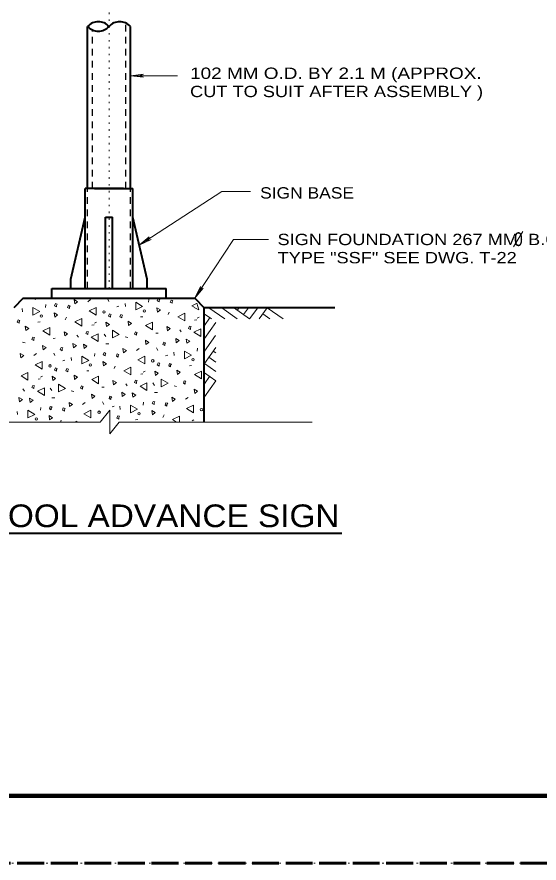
# Model space of a CAD drawing. Extents: x 312583 to 312854, y 144419 to 144597.
# Drawn here: x 312766.7 to 312801.7, y 144418.6 to 144475.3 of the extents above; entities that cross this region are included whole.
import ezdxf
from ezdxf.enums import TextEntityAlignment as Align

# ---------------------------------------------------------------- set-up
doc = ezdxf.new("R2010")
doc.units = 0
doc.header["$LTSCALE"] = 0.3
for name, pattern in [('DOTTED', [1.5, 0.3, -1.2]), ('LONG_DASHED', [7.5, 6, -1.5]), ('SHORT_DASHED', [2.7, 1.5, -1.2])]:
    doc.linetypes.add(name, pattern=pattern)
for name, color, linetype, lineweight in [('1', 7, 'Continuous', 40), ('2', 7, 'Continuous', 13), ('62', 7, 'DOTTED', 13), ('63', 7, 'LONG_DASHED', 60)]:
    doc.layers.add(name, color=color, linetype=linetype, lineweight=lineweight)

msp = doc.modelspace()

# ---------------------------------------------------------------- linework, layer by layer
at = {"layer": '1', "linetype": 'DOTTED', "lineweight": 13}
msp.add_line((312772.852, 144457.0926), (312772.852, 144496.5069), dxfattribs=at)
at = {"layer": '1', "linetype": 'SHORT_DASHED', "lineweight": 25}
for p, q in [((312773.9713, 144463.8009), (312773.9713, 144474.8946)), ((312771.7326, 144463.8009), (312771.7326, 144474.4269)), ((312771.4183, 144457.0926), (312771.4183, 144463.8009)), ((312774.2933, 144457.0926), (312774.2933, 144463.8009))]:
    msp.add_line(p, q, dxfattribs=at)
at = {"layer": '1'}
for p, q in [((312771.4183, 144463.8009), (312771.4183, 144474.6646)), ((312774.2933, 144463.8009), (312774.2933, 144474.6646)), ((312771.2573, 144457.0926), (312771.2573, 144463.8009)), ((312773.8256, 144463.8009), (312771.2573, 144463.8009)), ((312771.8783, 144463.8009), (312774.4466, 144463.8009)), ((312774.4466, 144457.0926), (312774.4466, 144463.8009)), ((312770.299, 144457.7289), (312771.2573, 144461.8843)), ((312772.6143, 144461.8843), (312773.0896, 144461.8843)), ((312772.6143, 144457.0926), (312772.6143, 144461.8843)), ((312773.0896, 144457.0926), (312773.0896, 144461.8843)), ((312775.405, 144457.7289), (312774.4466, 144461.8843)), ((312770.299, 144457.0926), (312770.299, 144457.7289)), ((312770.299, 144457.0926), (312770.299, 144457.7289)), ((312775.405, 144457.0926), (312775.405, 144457.7289)), ((312769.0186, 144456.4563), (312769.0186, 144457.0926)), ((312769.0186, 144457.0926), (312776.6853, 144457.0926)), ((312776.6853, 144456.4563), (312776.6853, 144457.0926)), ((312767.102, 144456.4563), (312766.4656, 144455.8123)), ((312767.102, 144456.4563), (312778.602, 144456.4563)), ((312778.602, 144456.4563), (312779.2383, 144455.8123)), ((312787.9936, 144455.8123), (312779.2383, 144455.8123)), ((312779.2383, 144448.1456), (312779.2383, 144455.8123))]:
    msp.add_line(p, q, dxfattribs=at)
at = {"layer": '1', "lineweight": 158}
msp.add_line((312616.5, 144423.0846), (312849, 144423.0846), dxfattribs=at)
at = {"layer": '1'}
for centre, start, end in [((312772.1339, 144474.0125), 42.07502, 137.92498), ((312773.5714, 144474.0125), 42.07502, 137.92498), ((312772.1339, 144475.3103), 222.07502, 317.92498)]:
    msp.add_arc(centre, 0.9683, start, end, dxfattribs=at)
at = {"layer": '2'}
for p, q in [((312774.2933, 144471.3603), (312775.1596, 144471.4676)), ((312774.2933, 144471.3603), (312777.452, 144471.3603)), ((312774.2933, 144471.3603), (312775.1596, 144471.2529)), ((312775.1596, 144471.4676), (312774.8836, 144471.3603)), ((312775.1596, 144471.2529), (312774.8836, 144471.3603)), ((312780.419, 144463.6016), (312774.8836, 144459.9906)), ((312780.419, 144463.6016), (312782.351, 144463.6016)), ((312799.9739, 144459.8899), (312800.6102, 144460.9172)), ((312774.8836, 144459.9906), (312775.5506, 144460.5579)), ((312774.8836, 144459.9906), (312775.6733, 144460.3739)), ((312775.5506, 144460.5579), (312775.382, 144460.3126)), ((312775.6733, 144460.3739), (312775.382, 144460.3126)), ((312781.1933, 144460.3816), (312778.602, 144456.4563)), ((312781.1933, 144460.3816), (312783.5393, 144460.3816)), ((312778.602, 144456.4563), (312778.993, 144457.2383)), ((312778.993, 144457.2383), (312778.9316, 144456.9469)), ((312778.602, 144456.4563), (312779.1693, 144457.1156)), ((312779.1693, 144457.1156), (312778.9316, 144456.9469)), ((312767.194, 144456.4563), (312767.2016, 144456.3949)), ((312767.2016, 144456.3949), (312767.2783, 144456.4563)), ((312767.8916, 144456.4563), (312767.907, 144456.3566)), ((312767.907, 144456.3566), (312768.0373, 144456.4563)), ((312771.6023, 144456.3489), (312771.426, 144456.2109)), ((312772.76, 144456.3873), (312772.8443, 144456.2186)), ((312773.9253, 144456.0959), (312773.9483, 144455.8889)), ((312775.4893, 144456.1726), (312775.5123, 144456.3566)), ((312777.4366, 144456.4563), (312777.4443, 144456.4103)), ((312777.4443, 144456.4103), (312777.498, 144456.4563)), ((312778.4103, 144455.9273), (312778.7246, 144456.0959)), ((312778.8703, 144455.6589), (312778.7476, 144456.1113)), ((312767.033, 144455.7509), (312767.056, 144455.5439)), ((312768.597, 144455.8276), (312768.62, 144456.0193)), ((312773.3656, 144455.8659), (312773.5113, 144455.9043)), ((312776.8846, 144455.5133), (312776.808, 144455.3446)), ((312778.4026, 144455.9426), (312778.602, 144455.8199)), ((312778.6096, 144455.8123), (312778.8703, 144455.6589)), ((312780.6106, 144455.0533), (312779.5373, 144455.8123)), ((312781.4463, 144455.0533), (312780.4113, 144455.7969)), ((312782.282, 144455.0533), (312781.1933, 144455.8276)), ((312781.569, 144455.8123), (312781.4463, 144455.6436)), ((312782.1976, 144455.8123), (312781.868, 144455.3523)), ((312782.8263, 144455.8123), (312782.282, 144455.0533)), ((312783.455, 144455.8123), (312782.9106, 144455.0533)), ((312784.5206, 144455.0533), (312783.455, 144455.8123)), ((312769.9923, 144455.1683), (312769.9156, 144454.9996)), ((312774.968, 144455.1913), (312775.1213, 144455.1989)), ((312778.5943, 144454.9843), (312778.74, 144455.0073)), ((312778.763, 144455.1146), (312778.8933, 144455.1836)), ((312779.729, 144455.0533), (312779.2383, 144455.3983)), ((312779.246, 144454.6239), (312779.591, 144455.1069)), ((312783.639, 144455.0533), (312783.156, 144455.3983)), ((312768.0833, 144454.8463), (312768.229, 144454.8539)), ((312771.702, 144454.6393), (312771.8476, 144454.6623)), ((312771.8706, 144454.7696), (312772.001, 144454.8386)), ((312777.59, 144454.3249), (312777.6973, 144454.1869)), ((312779.246, 144453.7423), (312780.0126, 144454.8156)), ((312769.0953, 144453.7499), (312769.2486, 144453.7576)), ((312770.6976, 144453.9799), (312770.805, 144453.8419)), ((312772.5146, 144454.0413), (312772.6373, 144453.8803)), ((312773.9406, 144453.8496), (312774.1093, 144453.8036)), ((312775.9876, 144454.0949), (312776.141, 144454.1026)), ((312779.246, 144452.8989), (312779.9896, 144453.9416)), ((312767.056, 144453.5046), (312767.2246, 144453.4586)), ((312772.6296, 144453.3819), (312772.8366, 144453.3973)), ((312767.9913, 144452.7303), (312767.8073, 144452.5999)), ((312769.1413, 144452.7686), (312769.2256, 144452.5999)), ((312771.8706, 144452.5539), (312771.8936, 144452.7456)), ((312774.876, 144453.0753), (312774.6996, 144452.9449)), ((312776.026, 144453.1136), (312776.118, 144452.9449)), ((312776.6393, 144452.5923), (312776.785, 144452.6306)), ((312777.199, 144452.8223), (312777.222, 144452.6153)), ((312778.7553, 144452.8989), (312778.7783, 144453.0906)), ((312779.246, 144452.0709), (312780.0203, 144453.1519)), ((312780.0126, 144452.7839), (312779.8363, 144452.8989)), ((312769.747, 144452.2473), (312769.8926, 144452.2856)), ((312770.3066, 144452.4773), (312770.3296, 144452.2703)), ((312780.0126, 144451.5266), (312779.246, 144452.0709)), ((312780.0126, 144452.1553), (312779.545, 144452.4849)), ((312771.357, 144451.5726), (312771.5026, 144451.5803)), ((312773.266, 144451.8946), (312773.1893, 144451.7259)), ((312775.1443, 144451.4959), (312775.2746, 144451.5649)), ((312778.2416, 144451.9176), (312778.3873, 144451.9253)), ((312768.091, 144451.0206), (312768.2366, 144451.0436)), ((312768.2596, 144451.1509), (312768.3823, 144451.2199)), ((312774.9756, 144451.3656), (312775.1213, 144451.3886)), ((312780.0126, 144450.8979), (312779.246, 144451.4423)), ((312779.246, 144450.7139), (312779.591, 144451.1969)), ((312767.079, 144450.3613), (312767.1863, 144450.2233)), ((312768.896, 144450.4226), (312769.0186, 144450.2616)), ((312772.369, 144450.4763), (312772.5223, 144450.4839)), ((312773.9713, 144450.7063), (312774.0786, 144450.5683)), ((312775.7806, 144450.7676), (312775.9033, 144450.6066)), ((312777.2143, 144450.5759), (312777.383, 144450.5299)), ((312779.246, 144449.8323), (312780.0126, 144450.8979)), ((312770.322, 144450.2309), (312770.4983, 144450.1849)), ((312775.9033, 144450.1159), (312776.1103, 144450.1236)), ((312778.1496, 144449.8016), (312777.9733, 144449.6713)), ((312769.011, 144449.7709), (312769.218, 144449.7786)), ((312771.2573, 144449.4566), (312771.081, 144449.3263)), ((312772.415, 144449.5026), (312772.4993, 144449.3263)), ((312775.1443, 144449.2803), (312775.1673, 144449.4719)), ((312766.688, 144448.8586), (312766.711, 144448.6516)), ((312768.252, 144448.9353), (312768.275, 144449.1269)), ((312773.0513, 144449.1653), (312773.197, 144449.2036)), ((312773.5803, 144449.2036), (312773.6033, 144448.9966)), ((312757.649, 144448.1456), (312772.2616, 144448.1456)), ((312769.6473, 144448.2759), (312769.5936, 144448.1456)), ((312773.542, 144448.1456), (312786.4833, 144448.1456)), ((312774.6306, 144448.2989), (312774.7763, 144448.3066)), ((312776.5396, 144448.6209), (312776.463, 144448.4523)), ((312778.418, 144448.2223), (312778.5483, 144448.2913))]:
    msp.add_line(p, q, dxfattribs=at)
at = {"layer": '2', "lineweight": 40}
msp.add_line((312749.5561, 144440.7036), (312788.4573, 144440.7036), dxfattribs=at)
at = {"layer": '2'}
for points in [[(312769.3253, 144455.9656), (312769.3713, 144456.0423), (312769.2563, 144456.0806), (312769.195, 144455.9273), (312769.3253, 144455.8583)], [(312770.552, 144456.0653), (312770.7436, 144456.2109), (312770.5136, 144456.3566)], [(312774.6383, 144456.1726), (312774.6383, 144455.6589), (312775.106, 144455.8966)], [(312776.2176, 144456.3106), (312776.2636, 144456.3873), (312776.1486, 144456.4256), (312776.0873, 144456.2723), (312776.2176, 144456.2033)], [(312777.084, 144456.2109), (312777.1376, 144456.2876), (312777.015, 144456.3259), (312776.9613, 144456.1726), (312777.084, 144456.1036)], [(312767.746, 144455.8276), (312767.746, 144455.3139), (312768.2136, 144455.5516)], [(312769.2103, 144455.1759), (312769.402, 144455.3293), (312769.172, 144455.4673)], [(312770.1993, 144455.8659), (312770.2453, 144455.9426), (312770.1303, 144455.9809), (312770.069, 144455.8276), (312770.1993, 144455.7586)], [(312771.978, 144455.3139), (312771.978, 144455.8276), (312771.5103, 144455.5976)], [(312776.1026, 144455.5209), (312776.2943, 144455.6743), (312776.0566, 144455.8123)], [(312766.8183, 144454.8846), (312766.8643, 144454.9613), (312766.7493, 144454.9996), (312766.688, 144454.8463), (312766.8183, 144454.7773)], [(312771.035, 144454.5779), (312771.035, 144455.0916), (312770.5673, 144454.8616)], [(312772.944, 144455.2756), (312772.99, 144455.3599), (312772.875, 144455.3983), (312772.8136, 144455.2449), (312772.944, 144455.1759)], [(312773.7106, 144455.2296), (312773.7566, 144455.3063), (312773.6416, 144455.3446), (312773.5803, 144455.1913), (312773.7106, 144455.1223)], [(312774.163, 144454.6163), (312774.3546, 144454.7619), (312774.1246, 144454.9076)], [(312777.9273, 144454.9229), (312777.9273, 144455.4366), (312777.4596, 144455.1989)], [(312767.2783, 144454.2713), (312767.47, 144454.4169), (312767.2323, 144454.5626)], [(312768.8806, 144453.9799), (312768.8806, 144454.4936), (312768.413, 144454.2636)], [(312772.6833, 144454.5396), (312772.8826, 144454.6853), (312772.645, 144454.8309)], [(312775.773, 144454.3249), (312775.773, 144454.8386), (312775.3053, 144454.6086)], [(312776.762, 144454.2636), (312776.9613, 144454.4093), (312776.7236, 144454.5473)], [(312778.3106, 144454.4553), (312778.3643, 144454.5396), (312778.2416, 144454.5703), (312778.188, 144454.4169), (312778.3106, 144454.3479)], [(312779.016, 144453.8879), (312779.016, 144454.4016), (312778.5483, 144454.1716)], [(312767.7996, 144453.7269), (312767.8456, 144453.8036), (312767.7306, 144453.8419), (312767.6693, 144453.6886), (312767.7996, 144453.6196)], [(312769.8773, 144453.9186), (312770.069, 144454.0643), (312769.839, 144454.2023)], [(312771.426, 144454.1103), (312771.472, 144454.1946), (312771.357, 144454.2253), (312771.2956, 144454.0719), (312771.426, 144454.0029)], [(312772.1236, 144453.5429), (312772.1236, 144454.0566), (312771.656, 144453.8266)], [(312773.0743, 144454.3019), (312773.0743, 144453.7806), (312773.542, 144454.0183)], [(312774.692, 144454.0719), (312774.738, 144454.1486), (312774.623, 144454.1869), (312774.5616, 144454.0336), (312774.692, 144453.9646)], [(312768.436, 144452.9909), (312768.6353, 144453.1366), (312768.3976, 144453.2823)], [(312770.4753, 144453.1213), (312770.667, 144453.2669), (312770.4293, 144453.4049)], [(312771.1806, 144453.0829), (312771.3723, 144453.2286), (312771.1346, 144453.3666)], [(312775.3283, 144453.3359), (312775.52, 144453.4816), (312775.29, 144453.6273)], [(312776.5933, 144453.3819), (312776.647, 144453.4586), (312776.5243, 144453.4969), (312776.4706, 144453.3436), (312776.5933, 144453.2746)], [(312777.36, 144453.4663), (312777.5516, 144453.6119), (312777.3216, 144453.7499)], [(312778.0653, 144453.4279), (312778.2646, 144453.5736), (312778.027, 144453.7116)], [(312766.9333, 144452.4466), (312767.1326, 144452.5999), (312766.895, 144452.7379)], [(312769.7086, 144453.0369), (312769.7546, 144453.1136), (312769.6396, 144453.1519), (312769.5783, 144452.9986), (312769.7086, 144452.9296)], [(312772.599, 144452.6919), (312772.645, 144452.7686), (312772.53, 144452.8069), (312772.4686, 144452.6536), (312772.599, 144452.5846)], [(312773.473, 144452.5923), (312773.519, 144452.6689), (312773.3963, 144452.7073), (312773.3426, 144452.5539), (312773.473, 144452.4849)], [(312773.8256, 144452.7916), (312774.0173, 144452.9449), (312773.7873, 144453.0829)], [(312777.912, 144452.8989), (312777.912, 144452.3853), (312778.3796, 144452.6229)], [(312768.3593, 144451.6953), (312768.3593, 144452.2089), (312767.8916, 144451.9789)], [(312771.0196, 144452.5539), (312771.0196, 144452.0403), (312771.4873, 144452.2779)], [(312772.484, 144451.9099), (312772.6756, 144452.0556), (312772.438, 144452.1936)], [(312775.2516, 144452.0403), (312775.2516, 144452.5539), (312774.784, 144452.3239)], [(312776.2176, 144452.0096), (312776.2636, 144452.0863), (312776.1486, 144452.1246), (312776.0873, 144451.9713), (312776.2176, 144451.9023)], [(312776.9843, 144451.9559), (312777.0303, 144452.0326), (312776.9076, 144452.0709), (312776.854, 144451.9176), (312776.9843, 144451.8486)], [(312769.3253, 144451.6646), (312769.3713, 144451.7413), (312769.2563, 144451.7796), (312769.195, 144451.6263), (312769.3253, 144451.5573)], [(312770.092, 144451.6109), (312770.138, 144451.6876), (312770.023, 144451.7259), (312769.9616, 144451.5726), (312770.092, 144451.5036)], [(312774.3086, 144451.3043), (312774.3086, 144451.8179), (312773.841, 144451.5879)], [(312775.957, 144451.2659), (312776.1486, 144451.4193), (312775.9186, 144451.5573)], [(312777.4366, 144451.3426), (312777.6283, 144451.4883), (312777.3983, 144451.6339)], [(312779.0466, 144451.0513), (312779.0466, 144451.5649), (312778.579, 144451.3349)], [(312767.4163, 144450.9593), (312767.4163, 144451.4729), (312766.9486, 144451.2429)], [(312769.0723, 144450.9209), (312769.264, 144451.0743), (312769.0263, 144451.2123)], [(312770.5443, 144450.9976), (312770.7436, 144451.1509), (312770.506, 144451.2889)], [(312772.1543, 144450.7063), (312772.1543, 144451.2199), (312771.6866, 144450.9899)], [(312773.151, 144450.6449), (312773.3426, 144450.7906), (312773.105, 144450.9286)], [(312774.6996, 144450.8366), (312774.7456, 144450.9209), (312774.6306, 144450.9516), (312774.5693, 144450.8059), (312774.6996, 144450.7293)], [(312776.348, 144451.0283), (312776.348, 144450.5146), (312776.8156, 144450.7446)], [(312767.8073, 144450.4916), (312767.8533, 144450.5759), (312767.7383, 144450.6066), (312767.677, 144450.4609), (312767.8073, 144450.3843)], [(312768.5126, 144449.9243), (312768.5126, 144450.4379), (312768.045, 144450.2079)], [(312769.4633, 144450.6833), (312769.4633, 144450.1696), (312769.9233, 144450.3996)], [(312771.0733, 144450.4533), (312771.1193, 144450.5299), (312771.0043, 144450.5683), (312770.943, 144450.4149), (312771.0733, 144450.3459)], [(312775.3973, 144450.2693), (312775.3973, 144450.7829), (312774.9296, 144450.5529)], [(312777.9656, 144450.7983), (312778.0116, 144450.8749), (312777.8966, 144450.9133), (312777.8353, 144450.7599), (312777.9656, 144450.6909)], [(312778.602, 144450.0623), (312778.7936, 144450.2156), (312778.5636, 144450.3536)], [(312766.8566, 144449.5026), (312767.0483, 144449.6483), (312766.8106, 144449.7939)], [(312771.7096, 144449.7173), (312771.9013, 144449.8706), (312771.6713, 144450.0086)], [(312772.9823, 144449.7633), (312773.0283, 144449.8399), (312772.9056, 144449.8783), (312772.852, 144449.7249), (312772.9823, 144449.6559)], [(312773.7413, 144449.8476), (312773.9406, 144449.9933), (312773.703, 144450.1389)], [(312774.4543, 144449.8093), (312774.646, 144449.9549), (312774.4083, 144450.0929)], [(312777.0993, 144449.5256), (312777.291, 144449.6713), (312777.061, 144449.8093)], [(312767.562, 144449.4643), (312767.7536, 144449.6099), (312767.5236, 144449.7479)], [(312770.207, 144449.1806), (312770.3986, 144449.3263), (312770.1686, 144449.4643)], [(312774.2933, 144449.2879), (312774.2933, 144448.7666), (312774.761, 144449.0043)], [(312775.8726, 144449.4183), (312775.9186, 144449.5026), (312775.8036, 144449.5333), (312775.7423, 144449.3799), (312775.8726, 144449.3109)], [(312776.739, 144449.3186), (312776.7926, 144449.4029), (312776.67, 144449.4336), (312776.6163, 144449.2803), (312776.739, 144449.2113)], [(312778.5253, 144448.7666), (312778.5253, 144449.2803), (312778.0576, 144449.0503)], [(312767.401, 144448.9429), (312767.401, 144448.4216), (312767.8686, 144448.6593)], [(312768.9803, 144449.0733), (312769.0263, 144449.1576), (312768.9113, 144449.1883), (312768.85, 144449.0349), (312768.9803, 144448.9659)], [(312769.8543, 144448.9736), (312769.9003, 144449.0579), (312769.7853, 144449.0886), (312769.724, 144448.9353), (312769.8543, 144448.8663)], [(312771.633, 144448.4216), (312771.633, 144448.9353), (312771.1653, 144448.7053)], [(312775.7576, 144448.6363), (312775.9493, 144448.7819), (312775.7116, 144448.9199)], [(312768.8653, 144448.2913), (312769.057, 144448.4369), (312768.827, 144448.5749)], [(312773.5036, 144448.4446), (312773.5496, 144448.5289), (312773.4346, 144448.5596), (312773.3733, 144448.4063), (312773.5036, 144448.3373)]]:
    msp.add_lwpolyline(points, close=True, dxfattribs=at)
for points in [[(312773.542, 144448.1456), (312772.9056, 144447.3483), (312772.9056, 144448.9429), (312772.2616, 144448.1456)], [(312770.69, 144448.1456), (312770.69, 144448.1993), (312770.5826, 144448.1456)], [(312777.5746, 144448.1456), (312777.5823, 144448.5443), (312777.1146, 144448.3143), (312777.383, 144448.1456)], [(312779.2383, 144448.2529), (312779.1923, 144448.2836), (312779.2076, 144448.1456)]]:
    msp.add_lwpolyline(points, dxfattribs=at)
for centre, radius in [((312772.5111, 144455.5232), 0.0865), ((312775.2108, 144455.5936), 0.0784), ((312768.321, 144455.2489), 0.0784), ((312771.5935, 144451.9764), 0.0784), ((312775.7836, 144452.2506), 0.0865), ((312778.4834, 144452.3211), 0.0784), ((312768.8938, 144451.9059), 0.0865), ((312772.1824, 144448.8026), 0.0865), ((312774.8661, 144448.7038), 0.0784), ((312779.0562, 144448.978), 0.0865), ((312767.9763, 144448.3591), 0.0784)]:
    msp.add_circle(centre, radius, dxfattribs=at)
at = {"layer": '62'}
msp.add_lwpolyline([(312601.2, 144418.5846), (312853.5, 144418.5846), (312853.5, 144596.7846)], dxfattribs=at)
at = {"layer": '63'}
msp.add_line((312851.75, 144418.5846), (312583.526, 144418.5846), dxfattribs=at)

# ---------------------------------------------------------------- texts
at = {"layer": '2'}
for s, width, p in [('102 MM O.D. BY 2.1 M (APPROX.', 1.25, (312778.2876, 144471.1446)), ('CUT TO SUIT AFTER ASSEMBLY )', 1.2, (312778.2876, 144469.9246)), ('SIGN BASE ', 1.15, (312782.9842, 144463.1253)), ('SIGN FOUNDATION 267 MM  B.C.', 1.2, (312784.1526, 144460.0049)), ('TYPE "SSF" SEE DWG. T-22', 1.2, (312784.1526, 144458.7849))]:
    msp.add_text(s, height=0.76, dxfattribs=dict(at, width=width)).set_placement(p)
for s, height, width, p in [('0', 0.92, 0.85, (312800.3112, 144459.9436)), ('FLASHING SCHOOL ADVANCE SIGN', 1.52, 1.1, (312768.9265, 144441.102))]:
    msp.add_text(s, height=height, dxfattribs=dict(at, width=width)).set_placement(p, align=Align.CENTER)

doc.saveas('drawing.dxf')
